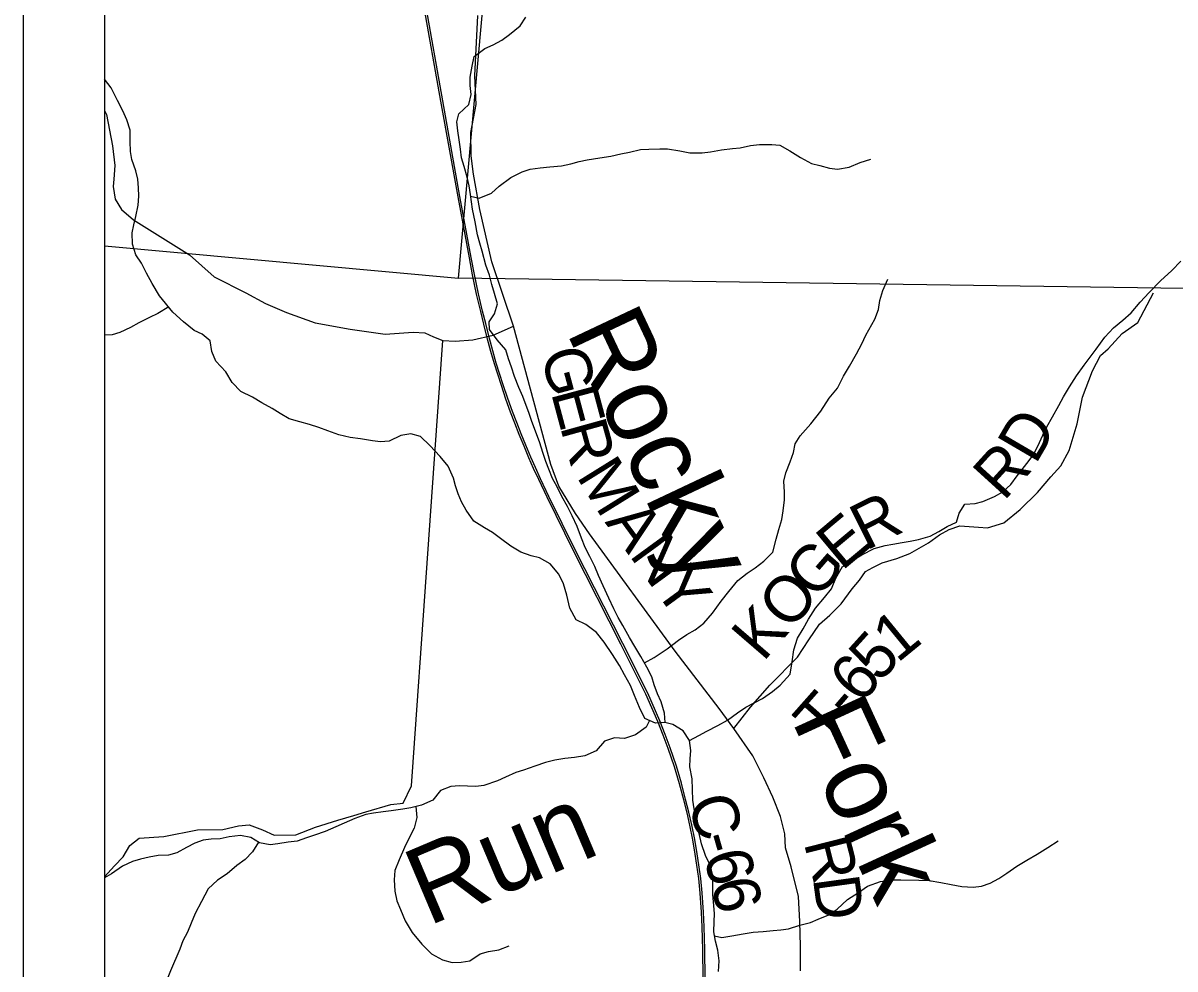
# Model space of a CAD drawing. Extents: x 0 to 40.8, y 0 to 22.
# Drawn here: x 2 to 3.414, y 17.538 to 18.699 of the extents above; entities that cross this region are included whole.
import ezdxf

# ---------------------------------------------------------------- set-up
doc = ezdxf.new("R2010")
doc.units = 0
for name, color, linetype in [('Default', 7, 'Continuous'), ('GM_X_County_Road', 7, 'Continuous'), ('GM_X_County_Road_Text', 7, 'Continuous'), ('GM_X_Minor_River', 7, 'Continuous'), ('GM_X_Minor_River_Text', 7, 'Continuous'), ('GM_X_Rail_Line', 7, 'Continuous'), ('GM_X_Section', 7, 'Continuous'), ('GM_X_Township_Road', 7, 'Continuous'), ('GM_X_Township_Road_Text', 7, 'Continuous'), ('SH_Cut_Line', 7, 'Continuous'), ('SH_Data', 7, 'Continuous')]:
    doc.layers.add(name, color=color, linetype=linetype)

msp = doc.modelspace()

# ---------------------------------------------------------------- linework, layer by layer
at = {"layer": 'Default'}
msp.add_lwpolyline([(3.6829, 20.9), (2.1, 20.9), (2.1, 17.4153), (2.4594, 17.3966), (2.8463, 17.3693), (2.8484, 17.3691), (3.1244, 17.3534), (3.4481, 17.3334), (3.5638, 19.132), (3.5742, 19.2945), (3.575, 19.3064), (3.6386, 20.2396), (3.6672, 20.5588), (3.6703, 20.6733)], close=True, dxfattribs=at)
at = {"layer": 'GM_X_County_Road'}
msp.add_lwpolyline([(2.1, 19.4381), (2.1, 18.4259), (2.5343, 18.3862), (2.6264, 19.4085)], close=True, dxfattribs=at)
for points in [[(2.9542, 17.5362), (2.9543, 17.5663), (2.9534, 17.5967), (2.952, 17.6271), (2.9427, 17.6636), (2.936, 17.6872), (2.9349, 17.7043), (2.9297, 17.7256), (2.9204, 17.7492), (2.9091, 17.7729), (2.8956, 17.7999), (2.8726, 17.8335), (2.8545, 17.8579), (2.8005, 17.9285), (2.6953, 18.0724), (2.678, 18.0972), (2.6577, 18.1308), (2.6479, 18.1574), (2.6022, 18.3274), (2.5755, 18.4064), (2.5607, 18.4703), (2.5529, 18.5137), (2.55, 18.5365), (2.5498, 18.565), (2.556, 18.5995), (2.5547, 18.6345), (2.5581, 18.7086)], [(2.1, 18.592), (2.1023, 18.5872), (2.1097, 18.5484), (2.1126, 18.5245), (2.1113, 18.5078), (2.1105, 18.4986), (2.1131, 18.4831), (2.121, 18.4705), (2.1354, 18.4578), (2.2043, 18.4149), (2.2345, 18.3877), (2.2735, 18.3681), (2.2974, 18.3551), (2.3235, 18.3439), (2.3584, 18.3312), (2.4016, 18.3237), (2.4445, 18.3174), (2.4787, 18.3199), (2.4931, 18.319), (2.5037, 18.314), (2.5151, 18.3098), (2.5303, 18.3089), (2.5519, 18.3103), (2.577, 18.3163), (2.6022, 18.3274)], [(2.1, 17.6516), (2.1124, 17.6648), (2.123, 17.6758), (2.1311, 17.6898), (2.1425, 17.6988), (2.1729, 17.701), (2.2143, 17.7091), (2.2451, 17.7097), (2.2645, 17.7141), (2.2774, 17.7152), (2.2941, 17.709), (2.3081, 17.7025), (2.335, 17.7031), (2.359, 17.7125), (2.3864, 17.7211), (2.4062, 17.7266), (2.4206, 17.7311), (2.4514, 17.7401), (2.4666, 17.7419), (2.4766, 17.7631), (2.5151, 18.3098)]]:
    msp.add_lwpolyline(points, dxfattribs=at)
at = {"layer": 'GM_X_Minor_River'}
for points in [[(2.788, 17.8407), (2.7874, 17.8522), (2.7831, 17.8663), (2.7788, 17.8762), (2.7748, 17.8869), (2.7716, 17.8969), (2.7658, 17.9088), (2.7584, 17.9218), (2.7511, 17.9341), (2.7445, 17.9452), (2.736, 17.9598), (2.7305, 17.9698), (2.7251, 17.9805), (2.7189, 17.9936), (2.712, 18.0085), (2.7065, 18.0211), (2.7018, 18.0322), (2.6956, 18.0445), (2.6901, 18.0556), (2.6854, 18.0671), (2.68, 18.0812), (2.6742, 18.0943), (2.6683, 18.1061), (2.6614, 18.1184), (2.6555, 18.1299), (2.65, 18.1403), (2.6453, 18.1518), (2.6417, 18.1613), (2.6382, 18.1724), (2.6342, 18.1839), (2.6302, 18.195), (2.6245, 18.2102), (2.6213, 18.2202), (2.6133, 18.2408), (2.6086, 18.2519), (2.6032, 18.2653), (2.5996, 18.2768), (2.596, 18.2871), (2.5924, 18.2982), (2.582, 18.3105), (2.5724, 18.3232), (2.5722, 18.3327), (2.5785, 18.3425), (2.5825, 18.3545), (2.5786, 18.3675), (2.5754, 18.3782), (2.5726, 18.3897), (2.5679, 18.4023), (2.5637, 18.4191), (2.5608, 18.429), (2.558, 18.4393), (2.5549, 18.4553), (2.5518, 18.4709), (2.5491, 18.4888), (2.5474, 18.4995), (2.545, 18.5102), (2.5414, 18.5231), (2.5382, 18.5338), (2.5369, 18.5445), (2.5352, 18.5559), (2.5335, 18.5669), (2.5326, 18.578), (2.5347, 18.5878), (2.547, 18.5993), (2.5499, 18.6114), (2.549, 18.6228), (2.5488, 18.6327), (2.5514, 18.6463), (2.5539, 18.6584), (2.567, 18.668), (2.5769, 18.6724), (2.5876, 18.6782), (2.5972, 18.6852), (2.61, 18.696), (2.617, 18.7065)], [(2.2099, 18.322), (2.1969, 18.3326), (2.1838, 18.3446), (2.1675, 18.3646), (2.1584, 18.3796), (2.1514, 18.3923), (2.1452, 18.4046), (2.1386, 18.4149), (2.1343, 18.4279), (2.1341, 18.442), (2.1359, 18.4518), (2.1383, 18.462), (2.1412, 18.4756), (2.1422, 18.4866), (2.1417, 18.4972), (2.1411, 18.5075), (2.1383, 18.5178), (2.1336, 18.5319), (2.1319, 18.5415), (2.1314, 18.554), (2.1313, 18.568), (2.1273, 18.5806), (2.1226, 18.5917), (2.116, 18.6044), (2.108, 18.6197), (2.1, 18.6303)], [(2.5494, 18.4867), (2.56, 18.4844), (2.5749, 18.4906), (2.5845, 18.4991), (2.5988, 18.5098), (2.6126, 18.5168), (2.6225, 18.52), (2.6347, 18.5217), (2.6464, 18.523), (2.6609, 18.5242), (2.6723, 18.5266), (2.6826, 18.5295), (2.6925, 18.5312), (2.7081, 18.5339), (2.7214, 18.5359), (2.7336, 18.5387), (2.7442, 18.5408), (2.7579, 18.5439), (2.7682, 18.5445), (2.7815, 18.545), (2.7909, 18.5448), (2.8061, 18.5426), (2.8185, 18.5401), (2.8337, 18.5398), (2.8436, 18.5411), (2.8573, 18.5438), (2.8706, 18.5451), (2.8804, 18.546), (2.893, 18.5488), (2.904, 18.5501), (2.9192, 18.5502), (2.929, 18.5493), (2.941, 18.5426), (2.9541, 18.5343), (2.9676, 18.5269), (2.9778, 18.5244), (2.9899, 18.5211), (2.9997, 18.5198), (3.0138, 18.5222), (3.0276, 18.528), (3.0406, 18.5323)], [(2.8179, 17.8189), (2.8294, 17.8248), (2.8393, 17.8303), (2.8527, 17.8372), (2.8646, 17.8438), (2.8769, 17.8527), (2.8873, 17.8597), (2.8976, 17.8648), (2.9076, 17.8703), (2.9199, 17.8788), (2.9295, 17.8865), (2.9415, 17.9003), (2.9441, 17.9151), (2.9459, 17.9299), (2.9507, 17.9442), (2.9574, 17.9558), (2.9641, 17.9675), (2.9727, 17.981), (2.9839, 17.9944), (2.9925, 18.0049), (2.9976, 18.018), (3.0059, 18.0323), (3.0159, 18.0386), (3.0297, 18.0466), (3.0446, 18.0543), (3.0583, 18.0582), (3.0678, 18.0595), (3.0789, 18.0616), (3.0888, 18.0633), (3.099, 18.0654), (3.1135, 18.0696), (3.1242, 18.0751), (3.1342, 18.0814), (3.1457, 18.0865), (3.149, 18.0978), (3.156, 18.1087), (3.1685, 18.1096), (3.178, 18.112), (3.1922, 18.1182), (3.2025, 18.1241), (3.2126, 18.133), (3.2204, 18.1435), (3.232, 18.1588), (3.2398, 18.1689), (3.2457, 18.1801), (3.2516, 18.1933), (3.2568, 18.2035), (3.2635, 18.2159), (3.2713, 18.2297), (3.2772, 18.2406), (3.2846, 18.2526), (3.2932, 18.2665), (3.3026, 18.2792), (3.31, 18.2893), (3.317, 18.2991), (3.3279, 18.3136), (3.3384, 18.3252), (3.3499, 18.3348), (3.36, 18.3438), (3.3712, 18.3568), (3.3824, 18.3684), (3.396, 18.3829), (3.4099, 18.3955), (3.4211, 18.4071)], [(2.7628, 17.914), (2.7747, 17.9207), (2.7905, 17.9314), (2.8047, 17.9418), (2.8147, 17.9488), (2.825, 17.9546), (2.8358, 17.9628), (2.8463, 17.9751), (2.8568, 17.9897), (2.8665, 18.0017), (2.8774, 18.0151), (2.8889, 18.024), (2.8986, 18.0306), (2.9093, 18.0388), (2.9205, 18.0499), (2.9243, 18.0658), (2.9275, 18.0775), (2.9312, 18.0899), (2.9329, 18.1005), (2.9347, 18.1142), (2.9348, 18.1237), (2.934, 18.137), (2.9364, 18.1472), (2.9416, 18.1607), (2.9456, 18.172), (2.9477, 18.183), (2.954, 18.1927), (2.9668, 18.2073), (2.9792, 18.223), (2.9894, 18.2387), (2.9995, 18.2511), (3.007, 18.2657), (3.0144, 18.2781), (3.0231, 18.2935), (3.0294, 18.3055), (3.0345, 18.3164), (3.0455, 18.3359), (3.0499, 18.3476), (3.0516, 18.3586), (3.0553, 18.371), (3.0616, 18.3849)], [(2.1788, 18.3508), (2.1656, 18.3427), (2.1553, 18.3379), (2.1423, 18.3314), (2.1319, 18.3255), (2.1189, 18.3193), (2.1094, 18.3168), (2.1, 18.3164)], [(2.8537, 17.5354), (2.8544, 17.5483), (2.8527, 17.5613), (2.8499, 17.5723), (2.8478, 17.5838), (2.8481, 17.5967), (2.8487, 17.6061), (2.8477, 17.6164), (2.8468, 17.6297), (2.8466, 17.6392), (2.8465, 17.6525), (2.8437, 17.6651), (2.8375, 17.6777), (2.8329, 17.6918), (2.8297, 17.7048), (2.8272, 17.7144), (2.8263, 17.7239), (2.8238, 17.7349), (2.8221, 17.7456), (2.8216, 17.7585), (2.8211, 17.7718), (2.8184, 17.7863), (2.819, 17.7961), (2.8195, 17.8064), (2.8179, 17.8189), (2.8101, 17.8308), (2.7974, 17.8383), (2.7876, 17.8408), (2.7762, 17.8402), (2.7634, 17.8458), (2.7565, 17.8592), (2.7507, 17.8738), (2.7456, 17.8864), (2.7383, 17.8994), (2.7321, 17.9109), (2.7236, 17.9244), (2.7133, 17.9394), (2.7037, 17.9513), (2.6909, 17.9611), (2.6789, 17.967), (2.6712, 17.9812), (2.6674, 17.9972), (2.6635, 18.011), (2.6576, 18.0229), (2.6469, 18.0356), (2.6338, 18.0431), (2.6236, 18.0455), (2.6111, 18.05), (2.5988, 18.0574), (2.5861, 18.0668), (2.5764, 18.0742), (2.5662, 18.0797), (2.5535, 18.0879), (2.5439, 18.1014), (2.538, 18.1118), (2.534, 18.1213), (2.5308, 18.1313), (2.5283, 18.1408), (2.5218, 18.1553), (2.5118, 18.1673), (2.4992, 18.1808), (2.488, 18.1917), (2.4759, 18.1953), (2.4638, 18.1929), (2.4492, 18.186), (2.4386, 18.1854), (2.4288, 18.1864), (2.4144, 18.189), (2.4015, 18.1907), (2.3876, 18.194), (2.374, 18.1989), (2.3631, 18.2029), (2.3518, 18.2065), (2.3397, 18.2098), (2.3265, 18.2135), (2.3157, 18.2201), (2.3059, 18.226), (2.2932, 18.2331), (2.2815, 18.2402), (2.2673, 18.2469), (2.2565, 18.2581), (2.2491, 18.2712), (2.2365, 18.2843), (2.2318, 18.2962), (2.2298, 18.3091), (2.2197, 18.3173), (2.2099, 18.322)], [(2.7689, 17.8434), (2.7647, 17.8351), (2.7517, 17.8259), (2.7383, 17.8212), (2.7258, 17.8219), (2.7136, 17.8179), (2.7035, 17.806), (2.6897, 17.7998), (2.6768, 17.7978), (2.665, 17.7965), (2.6529, 17.7945), (2.6414, 17.7917), (2.6281, 17.7874), (2.6143, 17.7823), (2.6048, 17.7795), (2.5922, 17.7736), (2.5822, 17.7693), (2.5654, 17.7635), (2.5559, 17.7622), (2.5457, 17.7628), (2.5358, 17.763), (2.5252, 17.7624), (2.5126, 17.7574), (2.5029, 17.7454), (2.4891, 17.7392), (2.4758, 17.7361), (2.4663, 17.7344), (2.4518, 17.7324), (2.442, 17.7311), (2.4302, 17.7294), (2.4207, 17.7281), (2.4073, 17.723), (2.3943, 17.7172), (2.384, 17.7129), (2.371, 17.707), (2.3576, 17.7024), (2.3481, 17.6991), (2.3366, 17.6952), (2.3256, 17.6939), (2.3127, 17.6919), (2.3032, 17.6905), (2.2903, 17.6931), (2.2798, 17.6997), (2.267, 17.7023), (2.2529, 17.7006), (2.2419, 17.6982), (2.2309, 17.6977), (2.221, 17.6963), (2.2107, 17.6927), (2.2007, 17.6876), (2.1889, 17.681), (2.1786, 17.6782), (2.1657, 17.6777), (2.155, 17.6756), (2.1443, 17.6732), (2.1344, 17.6703), (2.1222, 17.6645), (2.1087, 17.6553), (2.1, 17.6501)], [(2.4822, 17.7376), (2.4835, 17.7242), (2.4802, 17.711), (2.4732, 17.6978), (2.4684, 17.6873), (2.4617, 17.6722), (2.4565, 17.659), (2.4555, 17.6477), (2.4564, 17.634), (2.4588, 17.6218), (2.4632, 17.6115), (2.469, 17.5973), (2.4778, 17.5831), (2.4893, 17.5688), (2.5012, 17.5568), (2.5147, 17.5494), (2.5267, 17.5461), (2.5377, 17.5466), (2.5484, 17.5483), (2.5611, 17.5568), (2.5714, 17.5596), (2.5839, 17.5617), (2.5965, 17.5667)], [(2.2892, 17.6938), (2.2818, 17.6822), (2.2725, 17.6725), (2.2625, 17.6652), (2.2505, 17.6551), (2.2386, 17.6474), (2.2271, 17.6366), (2.2192, 17.6212), (2.2113, 17.6066), (2.2065, 17.5945), (2.2018, 17.5836), (2.1962, 17.5727), (2.1923, 17.5626), (2.1811, 17.5362), (2.1771, 17.526), (2.1735, 17.5147), (2.1668, 17.5008), (2.1613, 17.4888), (2.1545, 17.4741), (2.1482, 17.4602), (2.1415, 17.4486), (2.1321, 17.4317), (2.1239, 17.4208), (2.1115, 17.4084)], [(2.8487, 17.579), (2.8576, 17.5771), (2.8701, 17.5792), (2.8838, 17.5815), (2.896, 17.5836), (2.9085, 17.5845), (2.9207, 17.5854), (2.9302, 17.5863), (2.9397, 17.5876), (2.9534, 17.5919), (2.9664, 17.5955), (2.9759, 17.5995), (2.9889, 17.6049), (2.9993, 17.6119), (3.012, 17.6234), (3.0255, 17.6323), (3.0366, 17.64), (3.0526, 17.6458), (3.0667, 17.6478), (3.0773, 17.6479), (3.0997, 17.6475), (3.1122, 17.6469), (3.1266, 17.6443), (3.139, 17.6422), (3.1522, 17.6396), (3.1663, 17.6386), (3.1765, 17.6399), (3.1872, 17.6435), (3.1979, 17.6493), (3.2075, 17.656), (3.2198, 17.6645), (3.2321, 17.6718), (3.2448, 17.6792), (3.2578, 17.6873), (3.2705, 17.6957)]]:
    msp.add_lwpolyline(points, dxfattribs=at)
at = {"layer": 'GM_X_Rail_Line'}
for points in [[(2.8354, 17.4908), (2.8343, 17.5621), (2.8337, 17.5898), (2.8328, 17.6079), (2.8312, 17.6315), (2.8296, 17.6492), (2.8271, 17.6659), (2.8251, 17.6793), (2.822, 17.697), (2.8186, 17.7147), (2.815, 17.73), (2.811, 17.7459), (2.8058, 17.7656), (2.7996, 17.7863), (2.7919, 17.8089), (2.7857, 17.8251), (2.7792, 17.8419), (2.7646, 17.8757), (2.7339, 17.9368), (2.6759, 18.0507), (2.6433, 18.1172), (2.6329, 18.1389), (2.6265, 18.1526), (2.621, 18.1657), (2.615, 18.1801), (2.6091, 18.1943), (2.6037, 18.2082), (2.5985, 18.2217), (2.5926, 18.2377), (2.5871, 18.2543), (2.5827, 18.2685), (2.5786, 18.2812), (2.5743, 18.2961), (2.5701, 18.3115), (2.5656, 18.3298), (2.5618, 18.3452), (2.5567, 18.3664), (2.5517, 18.3901), (2.5478, 18.4112), (2.5339, 18.486), (2.513, 18.6034), (2.4911, 18.7253)], [(2.8378, 17.4908), (2.8367, 17.5622), (2.8362, 17.5899), (2.8353, 17.608), (2.8336, 17.6317), (2.832, 17.6495), (2.8295, 17.6663), (2.8275, 17.6797), (2.8244, 17.6974), (2.821, 17.7152), (2.8173, 17.7306), (2.8133, 17.7465), (2.8081, 17.7663), (2.8019, 17.7871), (2.7942, 17.8097), (2.788, 17.826), (2.7815, 17.8428), (2.7668, 17.8767), (2.736, 17.9379), (2.6781, 18.0518), (2.6454, 18.1183), (2.6351, 18.1399), (2.6288, 18.1536), (2.6232, 18.1666), (2.6172, 18.181), (2.6113, 18.1952), (2.6059, 18.2091), (2.6008, 18.2226), (2.5949, 18.2385), (2.5894, 18.2551), (2.585, 18.2692), (2.5809, 18.2819), (2.5766, 18.2968), (2.5725, 18.3121), (2.5679, 18.3304), (2.5641, 18.3457), (2.5591, 18.3669), (2.5541, 18.3906), (2.5501, 18.4116), (2.5363, 18.4864), (2.5154, 18.6038), (2.4935, 18.7257)]]:
    msp.add_lwpolyline(points, dxfattribs=at)
at = {"layer": 'GM_X_Section'}
msp.add_lwpolyline([(2.6264, 19.4085), (3.5805, 19.3077), (3.54, 18.3719), (2.5343, 18.3862)], close=True, dxfattribs=at)
at = {"layer": 'GM_X_Township_Road'}
msp.add_lwpolyline([(2.8726, 17.8335), (2.8928, 17.8596), (2.9165, 17.8868), (2.9505, 17.9212), (2.9646, 17.9424), (2.9776, 17.9614), (2.9902, 17.9727), (3.0043, 17.9863), (3.0177, 18.0049), (3.0265, 18.0154), (3.0342, 18.026), (3.0429, 18.0309), (3.0547, 18.0366), (3.0726, 18.0422), (3.0886, 18.0482), (3.1114, 18.0613), (3.1247, 18.0711), (3.1369, 18.0775), (3.1499, 18.082), (3.1726, 18.0804), (3.1836, 18.0799), (3.2038, 18.0859), (3.224, 18.1021), (3.245, 18.1233), (3.2614, 18.1422), (3.2736, 18.1558), (3.284, 18.1748), (3.294, 18.2074), (3.3003, 18.2401), (3.3126, 18.2723), (3.3225, 18.2912), (3.3321, 18.2995), (3.3489, 18.3181), (3.3683, 18.3316), (3.3875, 18.368)], dxfattribs=at)
at = {"layer": 'SH_Cut_Line'}
msp.add_lwpolyline([(7.7204, 20.9), (2.1, 20.9), (2.1, 17.4153), (2.4594, 17.3966), (2.8463, 17.3693), (2.8484, 17.3691), (3.1244, 17.3534), (3.4481, 17.3334), (4.5348, 17.2687), (4.8294, 17.2493), (5.3407, 17.2146), (5.6278, 17.197), (6.1785, 17.166), (6.9172, 17.1197), (7.4495, 17.0841), (7.4798, 17.5479), (7.4963, 17.9476), (7.5246, 18.2047), (7.5789, 18.8336), (7.595, 19.0259), (7.6007, 19.1025), (7.6007, 19.1071), (7.6192, 19.376), (7.7055, 20.511)], close=True, dxfattribs=at)
at = {"layer": 'SH_Data'}
for p, q in [((2, 21), (2, 14)), ((2.1, 20.9), (2.1, 14.1))]:
    msp.add_line(p, q, dxfattribs=at)

# ---------------------------------------------------------------- texts
at = {"layer": 'GM_X_County_Road_Text'}
for s, rotation, p in [('G', 284.9781, (2.6348, 18.2941)), ('E', 284.9816, (2.6478, 18.2458)), ('R', 285.5173, (2.6589, 18.2042)), ('M', 301.8274, (2.6785, 18.1431)), ('A', 306.2088, (2.7136, 18.0867)), ('N', 306.1297, (2.7432, 18.0464)), ('Y', 306.1217, (2.7726, 18.006)), ('C', 286.3721, (2.8153, 17.7443)), ('-', 286.1213, (2.8284, 17.6996)), ('R', 284.2597, (2.9581, 17.6933)), ('6', 285.3149, (2.8348, 17.6774)), ('6', 283.1666, (2.8439, 17.6442)), ('D', 277.7978, (2.9693, 17.6497))]:
    msp.add_text(s, height=0.0568, rotation=rotation, dxfattribs=at).set_placement(p)
at = {"layer": 'GM_X_Minor_River_Text'}
for s, height, rotation, p in [('Rocky', 0.0947, 295.2863, (2.6662, 18.3208)), ('Fork', 0.0947, 294.6859, (2.9428, 17.8441)), ('Run', 0.09469, 22.9198, (2.4969, 17.5904))]:
    msp.add_text(s, height=height, rotation=rotation, dxfattribs=at).set_placement(p)
at = {"layer": 'GM_X_Township_Road_Text'}
for s, rotation, p in [('D', 59.6957, (3.2426, 18.1563)), ('R', 47.7499, (3.2037, 18.1115)), ('R', 26.6733, (3.0345, 18.0513)), ('E', 39.8659, (3.0048, 18.026)), ('G', 49.0629, (2.9737, 17.9899)), ('O', 49.2525, (2.9411, 17.952)), ('K', 49.2462, (2.9085, 17.9142)), ('1', 39.2978, (3.073, 17.913)), ('5', 47.9524, (3.0512, 17.8886)), ('6', 50.3211, (3.0292, 17.8621)), ('T', 48.4597, (2.9845, 17.8111)), ('-', 49.146, (3.0131, 17.8435))]:
    msp.add_text(s, height=0.0568, rotation=rotation, dxfattribs=at).set_placement(p)

doc.saveas('drawing.dxf')
